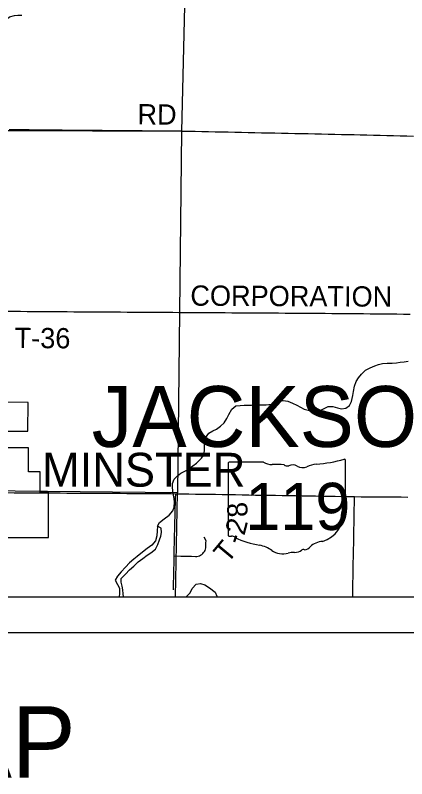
# Model space of a CAD drawing. Extents: x 0 to 34, y 0 to 22.
# Drawn here: x 6.279 to 7.376, y 13.591 to 15.728 of the extents above; entities that cross this region are included whole.
import ezdxf

# ---------------------------------------------------------------- set-up
doc = ezdxf.new("R2010")
doc.units = 0
for name, color, linetype in [('GM_X_Corporation', 7, 'Continuous'), ('GM_X_Corporation_Text', 7, 'Continuous'), ('GM_X_County_Road', 7, 'Continuous'), ('GM_X_County_Road_Text', 7, 'Continuous'), ('GM_X_Major_River', 7, 'Continuous'), ('GM_X_Minor_River', 7, 'Continuous'), ('GM_X_State_Location', 7, 'Continuous'), ('GM_X_State_Route', 7, 'Continuous'), ('GM_X_State_Shield', 7, 'Continuous'), ('GM_X_Township_Road', 7, 'Continuous'), ('GM_X_Township_Road_Text', 7, 'Continuous'), ('GM_X_Township_Text', 7, 'Continuous'), ('SH_Data', 7, 'Continuous'), ('SH_Text', 7, 'Continuous')]:
    doc.layers.add(name, color=color, linetype=linetype)

msp = doc.modelspace()

# ---------------------------------------------------------------- linework, layer by layer
at = {"layer": 'GM_X_Corporation'}
for points in [[(5.7675, 16.4186), (6.7694, 16.4145), (6.7449, 15.4031), (5.7454, 15.4068)], [(5.7454, 15.4068), (6.7449, 15.4031), (6.7333, 14.3908), (5.7313, 14.4009)], [(5.7241, 14.1), (6.7275, 14.1), (6.7333, 14.3908), (5.7313, 14.4009)]]:
    msp.add_lwpolyline(points, close=True, dxfattribs=at)
for points in [[(6.2347, 14.5639), (6.3139, 14.5634), (6.3151, 14.6439), (6.2359, 14.6444)], [(6.2255, 14.2659), (6.3721, 14.266), (6.372, 14.3925), (6.3483, 14.3925), (6.3483, 14.4494), (6.3157, 14.4496), (6.3156, 14.517), (6.2339, 14.517)], [(2.1, 14.1), (7.7244, 14.1)], [(2.1, 14.1), (7.7244, 14.1)]]:
    msp.add_lwpolyline(points, dxfattribs=at)
at = {"layer": 'GM_X_County_Road'}
msp.add_lwpolyline([(6.2615, 15.408), (6.2801, 15.4078), (6.2988, 15.4076), (6.3174, 15.4075), (6.336, 15.4073), (6.3547, 15.4071), (6.3733, 15.407), (6.392, 15.4068), (6.4106, 15.4066), (6.4292, 15.4065), (6.4479, 15.4063), (6.4665, 15.4062), (6.4852, 15.406), (6.5038, 15.4058), (6.5225, 15.4057), (6.5411, 15.4055), (6.5597, 15.4053), (6.5784, 15.4052), (6.597, 15.405), (6.6157, 15.4048), (6.6343, 15.4047), (6.6529, 15.4045), (6.6716, 15.4043), (6.6902, 15.4042), (6.7089, 15.404), (6.7272, 15.4039), (6.7455, 15.4037), (6.7641, 15.4033), (6.7828, 15.4029), (6.8014, 15.4025), (6.82, 15.4021), (6.8387, 15.4017), (6.8573, 15.4013), (6.8759, 15.401), (6.8946, 15.4006), (6.9132, 15.4002), (6.9318, 15.3998), (6.9505, 15.3994), (6.9691, 15.399), (6.9877, 15.3986), (7.0064, 15.3982), (7.025, 15.3978), (7.0437, 15.3974), (7.0623, 15.397), (7.0809, 15.3966), (7.0996, 15.3963), (7.1182, 15.3959), (7.1368, 15.3955), (7.1555, 15.3951), (7.1741, 15.3947), (7.1927, 15.3943), (7.2114, 15.3939), (7.2283, 15.3935), (7.2453, 15.3932), (7.264, 15.3927), (7.2826, 15.3922), (7.3012, 15.3918), (7.3199, 15.3913), (7.3385, 15.3908), (7.3571, 15.3904), (7.3758, 15.3899), (7.3944, 15.3894)], dxfattribs=at)
at = {"layer": 'GM_X_Major_River'}
for points in [[(6.6771, 14.2976), (6.6763, 14.2843), (6.6752, 14.2711), (6.6715, 14.2571), (6.6616, 14.2449), (6.6481, 14.2357), (6.6353, 14.2247), (6.6206, 14.2126), (6.6109, 14.2056), (6.5992, 14.1953), (6.5875, 14.1831), (6.5758, 14.1701), (6.5656, 14.1575), (6.5593, 14.1462), (6.5654, 14.1347), (6.5708, 14.1247), (6.5712, 14.1091), (6.5699, 14.1)], [(6.6879, 14.292), (6.6771, 14.2976)], [(6.5824, 14.1), (6.5814, 14.1081), (6.5805, 14.1195), (6.5789, 14.1298), (6.5758, 14.1413), (6.5761, 14.1511), (6.5874, 14.1637), (6.5991, 14.1752), (6.6112, 14.1862), (6.6236, 14.1981), (6.636, 14.2076), (6.6484, 14.2168), (6.6584, 14.223), (6.6716, 14.2336), (6.678, 14.2463), (6.6829, 14.2591), (6.6866, 14.2697), (6.6884, 14.2799), (6.6879, 14.292)], [(6.7575, 14.1), (6.7692, 14.1108), (6.7749, 14.1235), (6.7862, 14.135), (6.7977, 14.1377), (6.8105, 14.134), (6.8235, 14.1249), (6.8387, 14.1127), (6.8441, 14.1016), (6.8451, 14.1)]]:
    msp.add_lwpolyline(points, dxfattribs=at)
at = {"layer": 'GM_X_Minor_River'}
for points in [[(6.1168, 15.73), (6.1214, 15.72), (6.1302, 15.7077), (6.1406, 15.6998), (6.1533, 15.693), (6.1681, 15.6911), (6.1781, 15.6965), (6.1896, 15.7023), (6.2003, 15.7028), (6.2135, 15.7017), (6.2264, 15.701), (6.236, 15.7041), (6.2498, 15.7125), (6.263, 15.7232), (6.2764, 15.7266), (6.2859, 15.7275), (6.2977, 15.7283)], [(6.6772, 14.2976), (6.6831, 14.3081), (6.6962, 14.3187), (6.7105, 14.3282), (6.7207, 14.3409), (6.724, 14.3514), (6.7248, 14.3654), (6.7243, 14.3753), (6.7223, 14.3848), (6.7203, 14.3963), (6.7191, 14.4069), (6.7197, 14.4168), (6.7242, 14.4292), (6.7336, 14.4388), (6.7432, 14.4458), (6.754, 14.4519), (6.764, 14.4574), (6.7764, 14.4665), (6.7865, 14.4742), (6.8009, 14.4883), (6.8084, 14.4979), (6.8096, 14.5146), (6.8088, 14.5309), (6.8115, 14.5453), (6.8213, 14.5576), (6.8321, 14.5645), (6.8429, 14.5688), (6.8541, 14.5776), (6.8638, 14.5868), (6.8721, 14.5991), (6.877, 14.6107), (6.8853, 14.6253), (6.897, 14.6349), (6.9095, 14.6353), (6.9205, 14.6362), (6.93, 14.6367), (6.9406, 14.6368), (6.9566, 14.6375), (6.9676, 14.6372), (6.982, 14.6376), (6.9969, 14.6395), (7.008, 14.646), (7.0203, 14.6499), (7.0298, 14.6496), (7.0426, 14.6474), (7.0561, 14.6421), (7.0681, 14.6361), (7.0778, 14.6305), (7.0887, 14.6253), (7.0992, 14.622), (7.109, 14.6195), (7.1188, 14.6185), (7.1284, 14.6201), (7.1422, 14.6258), (7.1553, 14.6327), (7.1685, 14.6331), (7.1817, 14.6293), (7.1927, 14.6264), (7.2052, 14.628), (7.2153, 14.6353), (7.2209, 14.6465), (7.2244, 14.6631), (7.2262, 14.6749), (7.2292, 14.6892), (7.2345, 14.7027), (7.2409, 14.7132), (7.2487, 14.7228), (7.2604, 14.7343), (7.2731, 14.7412), (7.2861, 14.7465), (7.2968, 14.75), (7.3075, 14.7532), (7.3208, 14.7536), (7.3353, 14.754), (7.3467, 14.7552), (7.357, 14.7568), (7.3684, 14.758), (7.3794, 14.7593)]]:
    msp.add_lwpolyline(points, dxfattribs=at)
at = {"layer": 'GM_X_State_Route'}
for points in [[(6.2296, 14.3918), (6.2385, 14.3918), (6.2571, 14.3916), (6.2757, 14.3915), (6.2944, 14.3914), (6.313, 14.3913), (6.3278, 14.3912), (6.3427, 14.3911)], [(6.3427, 14.3911), (6.355, 14.391), (6.3674, 14.3909)], [(6.3674, 14.3909), (6.386, 14.3908), (6.4047, 14.3907), (6.4233, 14.3906), (6.442, 14.3905), (6.4606, 14.3904), (6.4734, 14.3903)], [(6.4734, 14.3903), (6.4792, 14.3902), (6.4979, 14.3901), (6.5165, 14.39), (6.5352, 14.3899), (6.5538, 14.3898), (6.5724, 14.3897), (6.5911, 14.3896), (6.6097, 14.3894), (6.6284, 14.3893), (6.647, 14.3892), (6.6657, 14.3891), (6.6843, 14.389), (6.7029, 14.3889), (6.7157, 14.3888), (6.7284, 14.3887), (6.747, 14.3884), (6.7656, 14.3881), (6.7843, 14.3878), (6.8029, 14.3875), (6.8216, 14.3872), (6.8402, 14.3869), (6.8589, 14.3866), (6.8775, 14.3863), (6.8961, 14.386), (6.9148, 14.3857), (6.9334, 14.3854), (6.9521, 14.385), (6.9707, 14.3847), (6.9893, 14.3844), (7.008, 14.3841), (7.0266, 14.3838), (7.0453, 14.3835), (7.0639, 14.3832), (7.0825, 14.3829), (7.1012, 14.3826), (7.1198, 14.3823), (7.1385, 14.382), (7.1571, 14.3817), (7.1757, 14.3814), (7.1944, 14.381), (7.212, 14.3808), (7.2296, 14.3805), (7.2483, 14.3803), (7.2669, 14.3802), (7.2856, 14.3801), (7.3042, 14.3799), (7.3228, 14.3798), (7.3415, 14.3796), (7.3601, 14.3795), (7.3788, 14.3794)], [(7.2243, 14.1), (7.2244, 14.1014), (7.2247, 14.12), (7.2251, 14.1386), (7.2254, 14.1573), (7.2258, 14.1759), (7.2261, 14.1945), (7.2265, 14.2132), (7.2268, 14.2318), (7.2272, 14.2505), (7.2275, 14.2691), (7.2279, 14.2877), (7.2282, 14.3064), (7.2286, 14.325), (7.2289, 14.3436), (7.2293, 14.362), (7.2296, 14.3805)]]:
    msp.add_lwpolyline(points, dxfattribs=at)
at = {"layer": 'GM_X_State_Shield'}
for p, q in [((6.8751, 14.4732), (6.8751, 14.2731)), ((6.9748, 14.4766), (6.8783, 14.4766)), ((7.2046, 14.3769), (7.2046, 14.4816)), ((7.2046, 14.3769), (7.2046, 14.3769))]:
    msp.add_line(p, q, dxfattribs=at)
for centre, major_axis, start_param, end_param in [((6.8788, 14.4736), (0.00382, 0), 1.712693, 3.28349), ((6.9978, 14.4999), (0.037, 0), 4.042523, 4.731795), ((7.0101, 14.3643), (0.133, 0), 1.404758, 1.657858), ((7.0403, 14.4747), (0.0107, 0), 3.836095, 5.185415), ((7.056, 14.4515), (0.0222, 0), 0.950623, 2.079405), ((7.0846, 14.4833), (0.0267, 0), 4.081561, 5.145723), ((7.1318, 14.4155), (0.0703, 0), 1.699011, 2.107814), ((7.0872, 14.7495), (0.3495, 0), 4.814394, 5.042369), ((7.201, 14.482), (0.00367, 0), 6.141152, 7.989035), ((7.2038, 14.3692), (0.00568, 0), 1.883978, 3.671073), ((7.1677, 14.356), (0.0341, 0), 5.934695, 6.695948), ((7.2007, 14.3765), (0.00393, 0), 5.05454, 6.418171), ((7.2178, 14.3331), (0.0248, 0), 2.387724, 3.262537), ((7.1068, 14.3198), (0.0874, 0), 5.101752, 6.440018), ((6.8789, 14.2726), (0.00385, 0), 3.00124, 4.508301), ((6.8795, 14.2931), (0.0294, 0), 4.665946, 4.897461), ((6.8855, 14.2615), (0.0106, 0), 0.519207, 1.627899), ((7.0193, 14.4413), (0.2524, 0), 4.195997, 4.488961), ((7.1437, 14.2169), (0.0479, 0), 1.647645, 2.488434), ((6.944, 14.1832), (0.079, 0), 0.823519, 1.323587), ((7.0862, 14.2262), (0.00752, 0), 1.147584, 2.315152), ((7.083, 14.2537), (0.0282, 0), 4.937069, 5.64225), ((7.0295, 14.2605), (0.0501, 0), 4.026481, 4.996735), ((7.0584, 14.1913), (0.0412, 0), 1.495662, 1.94098), ((7.0621, 14.2456), (0.0267, 0), 4.691044, 5.507374)]:
    msp.add_ellipse(centre, major_axis=major_axis, ratio=0.8, start_param=start_param, end_param=end_param, dxfattribs=at)
at = {"layer": 'GM_X_Township_Road'}
for points in [[(6.2352, 14.898), (6.2379, 14.8994), (6.2565, 14.8993), (6.2751, 14.8992), (6.2938, 14.8991), (6.3124, 14.8989), (6.3311, 14.8988), (6.3497, 14.8987), (6.3683, 14.8986), (6.387, 14.8985), (6.4056, 14.8983), (6.4243, 14.8982), (6.4429, 14.8981), (6.4615, 14.898), (6.4802, 14.8979), (6.4841, 14.8978)], [(6.4841, 14.8978), (6.4988, 14.8977), (6.5175, 14.8976), (6.5361, 14.8975), (6.5548, 14.8974), (6.5734, 14.8972), (6.592, 14.8971), (6.6107, 14.897), (6.6293, 14.8969), (6.648, 14.8968), (6.6666, 14.8966), (6.6852, 14.8965), (6.7039, 14.8964), (6.7204, 14.8963), (6.7369, 14.8962), (6.7556, 14.8961), (6.7742, 14.8959), (6.7928, 14.8958), (6.8115, 14.8957), (6.8301, 14.8956), (6.8488, 14.8955), (6.8674, 14.8954), (6.8861, 14.8952), (6.9047, 14.8951), (6.9233, 14.895), (6.942, 14.8949), (6.9606, 14.8947), (6.9793, 14.8946), (6.9979, 14.8945), (7.0165, 14.8944), (7.0352, 14.8943), (7.0538, 14.8941), (7.0725, 14.894), (7.0911, 14.8939), (7.1097, 14.8938), (7.1284, 14.8937), (7.147, 14.8935), (7.1657, 14.8934), (7.1843, 14.8933), (7.203, 14.8932), (7.2195, 14.8931), (7.236, 14.893), (7.2546, 14.8927), (7.2733, 14.8925), (7.2919, 14.8923), (7.3105, 14.8921), (7.3292, 14.8919), (7.3478, 14.8917), (7.3665, 14.8915), (7.3851, 14.8912)], [(6.7219, 14.12), (6.7224, 14.1387), (6.7228, 14.1573), (6.7233, 14.1759), (6.7237, 14.1946), (6.724, 14.2045), (6.7242, 14.2145), (6.7246, 14.2331), (6.7251, 14.2518), (6.7255, 14.2704), (6.726, 14.289), (6.7264, 14.3077), (6.7269, 14.3263), (6.7273, 14.345), (6.7278, 14.3636), (6.7281, 14.3762), (6.7284, 14.3887)], [(6.7242, 14.2145), (6.7428, 14.2141), (6.7615, 14.2136), (6.7727, 14.2134), (6.784, 14.2131), (6.7877, 14.2133), (6.7913, 14.2139), (6.7949, 14.215), (6.7982, 14.2166), (6.8014, 14.2186), (6.8042, 14.221), (6.8067, 14.2237), (6.8089, 14.2267), (6.8106, 14.23), (6.8119, 14.2335), (6.8127, 14.2372), (6.813, 14.2409), (6.8133, 14.2509), (6.8134, 14.2567), (6.8083, 14.2674)]]:
    msp.add_lwpolyline(points, dxfattribs=at)
at = {"layer": 'SH_Data'}
for p, q in [((2.1, 14.1), (8.9, 14.1)), ((2.1, 14.1), (8.9, 14.1)), ((2, 14), (9, 14))]:
    msp.add_line(p, q, dxfattribs=at)

# ---------------------------------------------------------------- texts
at = {"layer": 'GM_X_Corporation_Text'}
msp.add_text('MINSTER', height=0.0947, rotation=0, dxfattribs=at).set_placement((6.3539, 14.4084))
at = {"layer": 'GM_X_County_Road_Text'}
msp.add_text('RD', height=0.05682, rotation=359.5054, dxfattribs=at).set_placement((6.6211, 15.4223))
at = {"layer": 'GM_X_State_Location'}
for s in ['s', 'r']:
    msp.add_text(s, height=0.000189, dxfattribs=at).set_placement((7.0361, 14.3598))
msp.add_text('119', height=0.000189, rotation=0, dxfattribs=at).set_placement((6.9693, 14.3461))
at = {"layer": 'GM_X_State_Shield'}
msp.add_text('119', height=0.13184, dxfattribs=at).set_placement((6.9235, 14.2872))
at = {"layer": 'GM_X_Township_Road_Text'}
for s, height, rotation, p in [('CORPORATION', 0.056818, 359.7101, (6.7694, 14.9148)), ('T-36', 0.05682, 359.6465, (6.277, 14.7963)), ('8', 0.0568, 95.3526, (6.9314, 14.3251)), ('2', 0.0568, 75.1907, (6.9207, 14.2697)), ('T', 0.0568, 50.1039, (6.8735, 14.1911)), ('-', 0.0568, 71.0652, (6.9118, 14.2433))]:
    msp.add_text(s, height=height, rotation=rotation, dxfattribs=at).set_placement(p)
at = {"layer": 'GM_X_Township_Text'}
msp.add_text('JACKSON', height=0.17045, rotation=0, dxfattribs=at).set_placement((6.4931, 14.5195))
at = {"layer": 'SH_Text'}
msp.add_text('LOCATION MAP', height=0.2, dxfattribs=at).set_placement((4.4269, 13.5938))

doc.saveas('drawing.dxf')
